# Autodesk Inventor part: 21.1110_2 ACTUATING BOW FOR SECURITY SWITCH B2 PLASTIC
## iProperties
Created: 2007-05
Part Number: 21.1110_2 ACTUATING BOW FOR SECURITY SWITCH B2 PLASTIC
Material: ABS Plastic
Document SubType Name: Modeling
Designer: Andy Moles
Density: 1.06 g/cm^3
Author: Andy Moles
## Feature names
1. Extrusion1
2. Chamfer1
3. Extrusion2
4. Extrusion3
